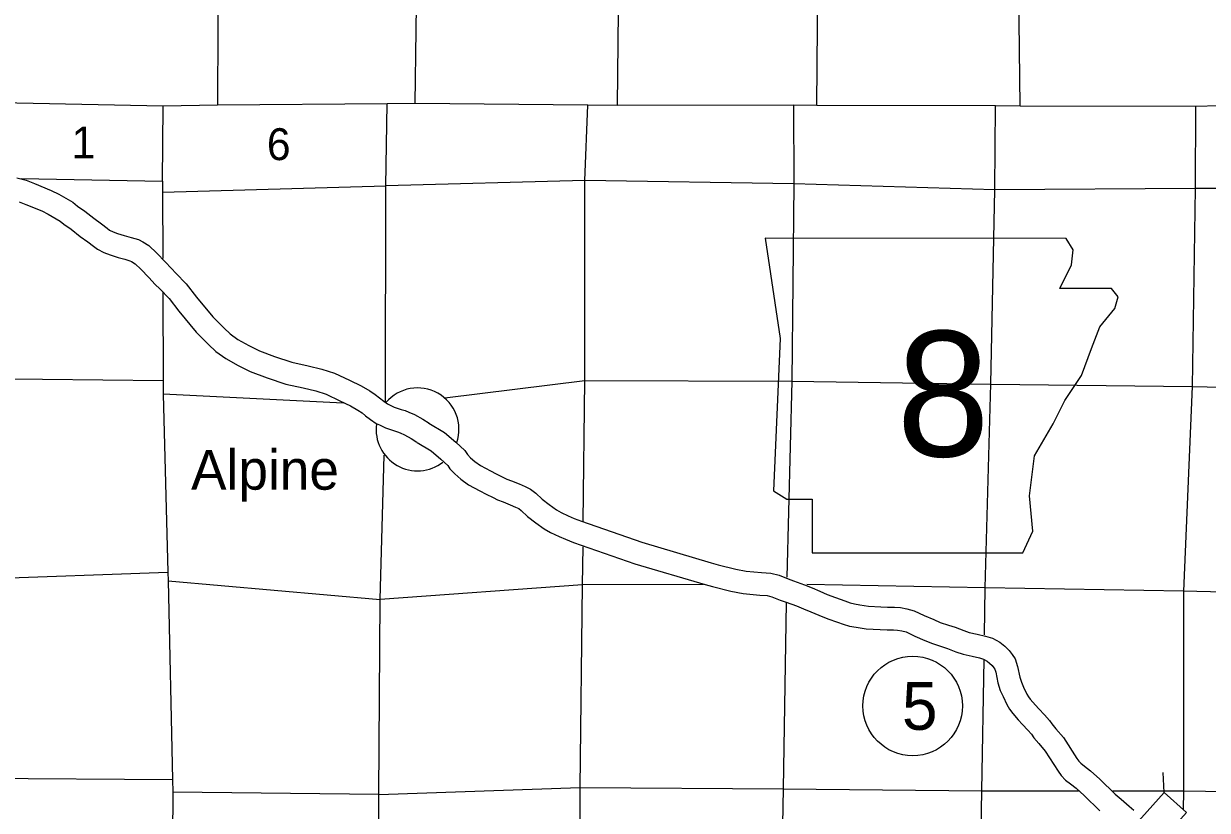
# Model space of a CAD drawing. Extents: x 369523 to 838377, y 495025 to 936819.
# Drawn here: x 480625 to 512038, y 804301 to 825177 of the extents above; entities that cross this region are included whole.
import ezdxf

# ---------------------------------------------------------------- set-up
doc = ezdxf.new("R2010")
doc.units = 0
for name, color, linetype in [('1', 7, 'Continuous'), ('22', 7, 'Continuous'), ('DSN_DRFT_Common-Line', 7, 'Continuous'), ('Level 1', 7, 'Continuous'), ('Level 15', 7, 'Continuous'), ('Level 21', 7, 'Continuous'), ('Level 22', 7, 'Continuous')]:
    doc.layers.add(name, color=color, linetype=linetype)

msp = doc.modelspace()

# ---------------------------------------------------------------- linework, layer by layer
at = {"layer": '1'}
for start, end in [(341.3667, 139.5954), (172.8519, 307.939)]:
    msp.add_arc((491077, 814411), 1100, start, end, dxfattribs=at)
at = {"layer": '22'}
msp.add_lwpolyline([(500305, 819484), (500705, 816819), (500527, 812778), (500882, 812556), (501548, 812556), (501548, 811135), (507144, 811135), (507411, 811712), (507322, 812645), (507455, 813711), (507943, 814555), (508254, 815176), (508698, 815842), (508965, 816553), (509187, 817130), (509587, 817619), (509675, 817930), (509498, 818152), (508121, 818152), (508432, 818774), (508476, 819173), (508292, 819480)], close=True, dxfattribs=at)
at = {"layer": 'DSN_DRFT_Common-Line'}
msp.add_circle((504219, 807071), 1320, dxfattribs=at)
at = {"layer": 'Level 1'}
for points in [[(480440, 821087), (480689, 821024), (480912, 820934), (481358, 820752), (481562, 820649), (481929, 820437), (482054, 820338), (482250, 820200), (482483, 820013), (482686, 819869), (482838, 819749), (482906, 819700), (482997, 819650), (483114, 819608), (483296, 819552), (483473, 819504), (483671, 819445), (483783, 819385), (483946, 819287), (484156, 819090), (484384, 818855), (484549, 818676), (484666, 818559), (484939, 818270), (485209, 817918), (485646, 817397), (485797, 817243), (485945, 817093), (486107, 816942), (486312, 816796), (486597, 816639), (486879, 816496), (487283, 816348), (487743, 816192), (488178, 816094), (488534, 816012), (488872, 815903), (489275, 815714), (489585, 815566), (489811, 815431), (489956, 815337), (490072, 815243), (490184, 815158), (490283, 815090), (490334, 815066), (490458, 815003), (490641, 814942), (490747, 814911), (490849, 814870), (490998, 814805), (491219, 814681), (491385, 814572)], [(480502, 820452), (480686, 820378), (481109, 820206), (481276, 820121), (481592, 819939), (481694, 819858), (481888, 819721), (482122, 819533), (482327, 819388), (482476, 819271), (482586, 819191), (482749, 819102), (482922, 819039), (483130, 818975), (483310, 818926), (483441, 818887), (483487, 818863), (483582, 818806), (483735, 818662), (483948, 818442), (484117, 818259), (484236, 818141), (484482, 817881), (484741, 817543), (485201, 816994), (485369, 816822), (485527, 816662), (485727, 816476), (485992, 816287), (486316, 816109), (486639, 815945), (487084, 815782), (487581, 815613), (488045, 815509), (488374, 815434), (488651, 815344), (489018, 815172), (489301, 815037), (489495, 814920), (489604, 814850), (489700, 814773), (489832, 814671), (489983, 814568), (490070, 814527), (490227, 814448), (490463, 814369), (490550, 814344), (490616, 814317), (490730, 814267), (490908, 814167), (491058, 814070)], [(491374, 814579), (491794, 814331), (492096, 814068), (492336, 813847), (492408, 813742), (492485, 813659), (492602, 813557), (492751, 813450), (493011, 813307), (493162, 813232), (493356, 813137), (493447, 813090), (493568, 813044), (493771, 812965), (493931, 812893), (494076, 812825), (494217, 812716), (494383, 812559), (494571, 812415), (494764, 812277), (494888, 812206), (495079, 812115), (495235, 812049), (495425, 811970), (497027, 811418), (498874, 810870), (499058, 810820), (499521, 810702), (499803, 810649), (500208, 810610), (500457, 810597), (500674, 810538), (500910, 810442), (501059, 810392), (501349, 810289), (501552, 810204), (501756, 810117), (501952, 810031), (502171, 809947), (502422, 809860), (502563, 809808), (502672, 809778), (502818, 809751), (503042, 809717), (503376, 809699), (503547, 809695), (503738, 809695), (503897, 809681), (504065, 809651), (504257, 809599), (504525, 809471), (504776, 809361), (504951, 809289), (505170, 809218), (505350, 809159), (505572, 809072), (505720, 809022), (505933, 808976), (506149, 808925), (506334, 808868), (506532, 808761), (506661, 808655), (506778, 808541), (506857, 808437), (506941, 808320), (507004, 808116), (507059, 807836), (507103, 807702), (507163, 807572), (507250, 807385), (507288, 807317), (507340, 807252), (507474, 807092), (507566, 806990), (507714, 806839), (507847, 806688), (507911, 806592), (508020, 806466), (508221, 806230), (508577, 805677), (508627, 805605), (508678, 805553), (508775, 805477), (508939, 805352), (509184, 805129), (509589, 804733), (509751, 804597), (509960, 804412), (510091, 804306)], [(491069, 814063), (491441, 813843), (491696, 813620), (491880, 813452), (491938, 813367), (492067, 813228), (492230, 813086), (492430, 812942), (492733, 812775), (492897, 812694), (493087, 812601), (493203, 812541), (493352, 812484), (493539, 812411), (493681, 812348), (493762, 812310), (493827, 812260), (493993, 812102), (494214, 811933), (494440, 811771), (494610, 811674), (494832, 811568), (495003, 811495), (495213, 811409), (496844, 810846), (498709, 810294), (498904, 810240), (499392, 810116), (499719, 810054), (500163, 810012), (500361, 810001), (500482, 809968), (500703, 809879), (500864, 809825), (501131, 809730), (501318, 809651), (501518, 809566), (501724, 809476), (501966, 809383), (502220, 809295), (502377, 809237), (502538, 809192), (502719, 809159), (502981, 809120), (503353, 809099), (503541, 809095), (503713, 809095), (503817, 809086), (503932, 809065), (504047, 809034), (504275, 808925), (504541, 808809), (504743, 808725), (504985, 808647), (505147, 808594), (505366, 808508), (505561, 808442), (505801, 808391), (505991, 808346), (506100, 808312), (506197, 808260), (506261, 808207), (506327, 808143), (506374, 808081), (506396, 808050), (506422, 807968), (506477, 807686), (506543, 807483), (506619, 807319), (506716, 807112), (506788, 806982), (506874, 806873), (507021, 806698), (507129, 806578), (507274, 806430), (507370, 806322), (507432, 806228), (507564, 806075), (507738, 805871), (508078, 805344), (508162, 805222), (508277, 805104), (508409, 805001), (508555, 804891), (508772, 804692), (509186, 804287)]]:
    msp.add_lwpolyline(points, dxfattribs=at)
at = {"layer": 'Level 15'}
for points in [[(495600, 823018), (491017, 823058), (490269, 823052), (485771, 823011), (484327, 822986), (480442, 823068), (479560, 823076), (475398, 823152)], [(484312, 820996), (484327, 822986)], [(512349, 822995), (511727, 822981), (507069, 822990), (506417, 822996), (501674, 823007), (501054, 823011), (496377, 823008), (495600, 823018)], [(484312, 820996), (484312, 820703), (484317, 818945)], [(484319, 818053), (484325, 815703), (484331, 815343), (484448, 810619), (484459, 810389), (484578, 805115), (484587, 804785), (484549, 799938), (484552, 799513), (484532, 794547), (484512, 789235), (484505, 789195), (484501, 783959), (484500, 783908), (484508, 778680), (484509, 778574)]]:
    msp.add_lwpolyline(points, dxfattribs=at)
at = {"layer": 'Level 21'}
msp.add_line((510897, 804776), (510869, 805303), dxfattribs=at)
msp.add_lwpolyline([(510897, 804776), (509311, 803007), (509900, 802478), (511487, 804247)], close=True, dxfattribs=at)
at = {"layer": 'Level 22'}
for points in [[(507069, 822990), (507013, 828266), (507014, 829976)], [(485792, 829730), (485783, 828329), (485776, 825098)], [(501674, 823007), (501718, 828289), (501726, 828620)], [(491017, 823058), (491064, 826959)], [(496408, 826348), (496377, 823008)], [(485776, 825098), (485771, 823011)], [(490236, 820875), (490269, 823052)], [(495477, 811960), (495520, 815704), (495518, 821015), (495600, 823018)], [(501054, 823011), (501064, 820927), (501011, 815691), (500878, 810485)], [(506126, 808958), (506146, 810207), (506292, 815616), (506397, 820767), (506417, 822996)], [(511727, 822981), (511715, 820801), (511637, 815546), (511407, 810118), (511403, 804821), (511397, 804315)], [(480559, 821070), (484312, 820996)], [(484312, 820703), (490236, 820875)], [(490224, 815133), (490236, 820875)], [(528869, 820393), (527758, 820459), (522479, 820723), (516877, 820803), (511715, 820801), (506397, 820767), (501064, 820927), (495518, 821015), (490236, 820875)], [(453024, 816150), (458246, 816000), (463524, 815861), (468831, 815890), (474266, 815872), (479511, 815757), (484325, 815703)], [(491805, 815247), (495520, 815704), (501011, 815691), (506302, 815610), (511637, 815546), (516782, 815434), (522406, 815341), (524645, 815277)], [(489107, 815108), (484331, 815343)], [(490016, 794476), (490030, 799503), (490046, 804722), (490085, 809896), (490188, 813723)], [(495279, 794399), (495367, 799673), (495397, 804909), (495458, 810288), (495469, 811292)], [(452871, 810816), (458173, 810724), (463493, 810588), (468776, 810626), (474307, 810595), (479517, 810441), (484448, 810619)], [(484459, 810389), (490085, 809896)], [(498669, 810295), (495458, 810288), (490085, 809896)], [(532878, 809844), (527711, 809901), (522375, 809979), (516768, 809983), (511407, 810118), (506146, 810207), (501405, 810290)], [(500865, 809812), (500780, 804868), (500685, 799663), (500567, 794404)], [(505832, 794343), (505961, 799548), (506057, 804815), (506115, 808299)], [(469639, 805289), (474220, 805222), (479458, 805157), (484578, 805115)], [(490046, 804722), (495397, 804909), (500780, 804868), (506057, 804815), (508615, 804818)], [(490046, 804722), (484587, 804785)], [(509527, 804819), (511403, 804821), (516700, 804742), (522370, 804678), (527661, 804659), (532891, 804546)]]:
    msp.add_lwpolyline(points, dxfattribs=at)

# ---------------------------------------------------------------- texts
at = {"layer": '1'}
msp.add_text('Alpine', height=1056, dxfattribs=at).set_placement((485067, 812810))
at = {"layer": '22'}
msp.add_text('8', height=3326, dxfattribs=at).set_placement((503790, 813693))
at = {"layer": 'DSN_DRFT_Common-Line'}
msp.add_text('5', height=1267, dxfattribs=at).set_placement((503935, 806437))
at = {"layer": 'Level 22'}
for s, p in [('1', (481896, 821602)), ('6', (487079, 821556))]:
    msp.add_text(s, height=845, dxfattribs=at).set_placement(p)

doc.saveas('drawing.dxf')
